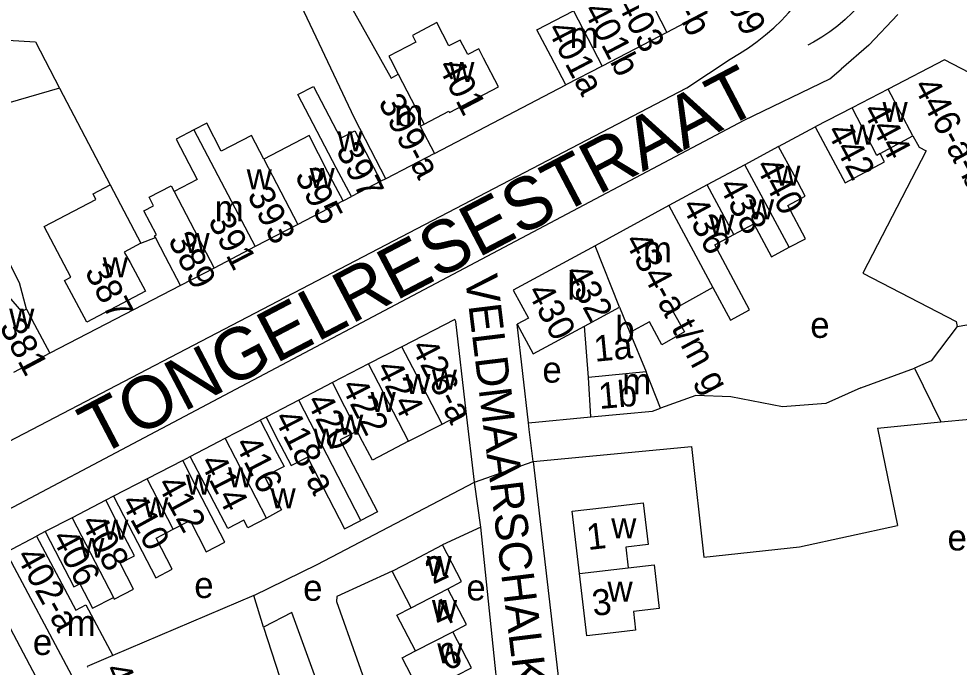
# Model space of a CAD drawing. Extents: x 163012 to 165277, y 382513 to 383987.
# Drawn here: x 163588.9 to 163733.4, y 383715.3 to 383815 of the extents above; entities that cross this region are included whole.
import ezdxf

# ---------------------------------------------------------------- set-up
doc = ezdxf.new("R2010")
doc.units = 0
for name, color, linetype in [('BLT_Basislijn', 7, 'Continuous'), ('BLT_Bebouwing', 7, 'Continuous'), ('BLT_Centroide', 7, 'Continuous'), ('BLT_Huisnummer', 7, 'Continuous'), ('BLT_Huisnummer_ tussenligend', 7, 'Continuous'), ('BLT_Huisnummer_reeks', 7, 'Continuous'), ('BLT_Onderverdeling_panden', 7, 'Continuous'), ('BLT_Straatnaam', 7, 'Continuous'), ('BLT_Straatnaam_hoofdweg', 7, 'Continuous'), ('BLT_Vlakafsluiter', 7, 'Continuous')]:
    doc.layers.add(name, color=color, linetype=linetype)

msp = doc.modelspace()

# ---------------------------------------------------------------- linework, layer by layer
at = {"layer": 'BLT_Basislijn'}
for p, q in [((163595.13, 383804.29), (163602.91, 383789.43)), ((163652.74, 383794.27), (163672.95, 383804.8)), ((163705.66, 383795.33), (163711.29, 383798.35)), ((163645.3, 383790.39), (163644.53, 383789.99)), ((163638.71, 383786.98), (163640.01, 383787.64)), ((163607.64, 383780.47), (163609.87, 383781.33)), ((163613.7, 383773.96), (163593.62, 383763.57)), ((163667.19, 383752.84), (163665.48, 383768.03)), ((163718.3, 383758.26), (163726.54, 383761.26)), ((163726.54, 383761.26), (163730.58, 383753.03)), ((163626.86, 383753.75), (163625.94, 383753.27)), ((163658.92, 383743.75), (163657.64, 383754.61)), ((163667.19, 383752.84), (163676.82, 383753.8)), ((163720.86, 383752.02), (163730.58, 383753.03)), ((163720.86, 383752.02), (163723.95, 383737.07)), ((163667.93, 383746.93), (163692.29, 383749.24)), ((163614.05, 383747.07), (163615.22, 383747.71)), ((163659.91, 383736.81), (163658.92, 383743.75)), ((163603.42, 383741.59), (163602.22, 383740.95)), ((163592.92, 383736.15), (163591.58, 383735.46)), ((163659.91, 383736.81), (163654, 383734.09)), ((163708.88, 383733.81), (163723.95, 383737.07)), ((163582.55, 383730.64), (163601.48, 383694.92))]:
    msp.add_line(p, q, dxfattribs=at)
for points in [[(163724.01, 383827.24), (163723.51, 383825.83), (163722.94, 383824.44), (163722.29, 383823.09), (163721.57, 383821.78), (163720.79, 383820.5), (163719.93, 383819.27), (163719.02, 383818.09), (163718.04, 383816.95), (163716.99, 383815.87), (163715.9, 383814.85), (163714.75, 383813.89), (163713.55, 383812.99), (163712.31, 383812.16), (163711.02, 383811.39), (163710.14, 383810.92)], [(163698.23, 383808.79), (163699.65, 383809.62), (163701.04, 383810.51), (163702.38, 383811.47), (163703.67, 383812.49), (163704.91, 383813.58), (163706.1, 383814.72), (163707.23, 383815.92), (163708.3, 383817.18), (163709.31, 383818.48), (163710.25, 383819.83), (163711.13, 383821.23), (163711.93, 383822.67), (163712.67, 383824.14), (163713.34, 383825.65), (163713.61, 383826.32)], [(163723.98, 383815.66), (163719.52, 383810.92), (163715.26, 383807.23)], [(163467.08, 383686.66), (163482.06, 383695.06), (163497.86, 383703.08), (163529.23, 383719.71), (163691.55, 383804.36), (163698.23, 383808.79)], [(163427.43, 383650.86), (163437.95, 383656.9), (163455.03, 383666.99), (163471.53, 383677.31), (163495.84, 383691.23), (163505.72, 383695.8), (163549.29, 383719.48), (163576.55, 383733.91), (163700.36, 383799.41), (163713.52, 383805.75), (163715.26, 383807.23)], [(163590.02, 383770.34), (163588.94, 383774.36), (163582.58, 383786.87)], [(163733.1, 383767.67), (163729.14, 383762.41), (163726.54, 383761.26)], [(163718.3, 383758.26), (163712.93, 383755.83), (163706.26, 383755.3)], [(163730.58, 383753.03), (163739.54, 383753.86), (163759.18, 383758.11)], [(163706.26, 383755.3), (163698.31, 383756.87), (163692.92, 383757.08), (163687.51, 383755.13)], [(163667.93, 383746.93), (163667.31, 383751.85), (163667.19, 383752.84)], [(163692.29, 383749.24), (163694.15, 383732.2), (163708.88, 383733.81)], [(163667.93, 383746.93), (163674.89, 383687.03), (163677.03, 383683.37), (163679.74, 383681.51), (163681.27, 383680.98), (163685.7, 383680.74)], [(163624.97, 383726.31), (163634.7, 383731.1), (163658.92, 383743.75)], [(163659.45, 383689.12), (163664.53, 383691.81), (163659.91, 383736.81)], [(163646.24, 383730.06), (163637.73, 383726.14), (163637.69, 383725.42), (163643.96, 383707.78), (163637.73, 383704.71)]]:
    msp.add_lwpolyline(points, dxfattribs=at)
at = {"layer": 'BLT_Bebouwing'}
for p, q in [((163695.01, 383816.28), (163688.49, 383812.89)), ((163688.49, 383812.89), (163678.52, 383807.7)), ((163731.14, 383808.68), (163722.48, 383804.17)), ((163735.02, 383806.65), (163731.14, 383808.68)), ((163678.52, 383807.7), (163672.95, 383804.8)), ((163595.13, 383804.29), (163575.89, 383798.75)), ((163722.48, 383804.17), (163716.96, 383801.3)), ((163716.96, 383801.3), (163711.29, 383798.35)), ((163721.25, 383794.28), (163726.32, 383796.99)), ((163705.66, 383795.33), (163700.47, 383792.54)), ((163652.74, 383794.27), (163645.3, 383790.39)), ((163700.47, 383792.54), (163694.69, 383789.43)), ((163644.53, 383789.99), (163640.01, 383787.64)), ((163602.91, 383789.43), (163607.64, 383780.47)), ((163694.69, 383789.43), (163688.78, 383786.26)), ((163638.71, 383786.98), (163631.75, 383783.36)), ((163688.78, 383786.26), (163677.47, 383780.07)), ((163631.75, 383783.36), (163625.21, 383779.96)), ((163698.8, 383781.79), (163701.84, 383783.43)), ((163607.64, 383780.47), (163605.07, 383779.11)), ((163625.21, 383779.96), (163618.87, 383776.66)), ((163618.87, 383776.66), (163613.7, 383773.96)), ((163718.61, 383775.89), (163732.96, 383768.43)), ((163695.57, 383773.66), (163698.27, 383768.65)), ((163732.96, 383768.43), (163733.1, 383767.67)), ((163676.43, 383759.84), (163675.81, 383767.73)), ((163682.8, 383766.74), (163685.31, 383760.72)), ((163593.62, 383763.57), (163588.02, 383760.6)), ((163647.76, 383764.57), (163642.63, 383761.92)), ((163642.63, 383761.92), (163637.07, 383759.04)), ((163687.51, 383755.13), (163685.31, 383760.72)), ((163676.82, 383753.8), (163676.43, 383759.84)), ((163637.07, 383759.04), (163631.89, 383756.35)), ((163631.89, 383756.35), (163626.86, 383753.75)), ((163620.58, 383750.49), (163625.94, 383753.27)), ((163614.05, 383747.07), (163608.58, 383744.25)), ((163608.58, 383744.25), (163603.42, 383741.59)), ((163602.22, 383740.95), (163597.05, 383738.28)), ((163597.05, 383738.28), (163592.92, 383736.15)), ((163586.94, 383733), (163591.58, 383735.46)), ((163591.58, 383735.46), (163597.62, 383724.04)), ((163596.99, 383714), (163586.94, 383733)), ((163649.16, 383724.43), (163646.24, 383730.06)), ((163624.97, 383726.31), (163603.29, 383717.08)), ((163626.49, 383721.47), (163624.97, 383726.31)), ((163597.62, 383724.04), (163599.17, 383724.86)), ((163599.17, 383724.86), (163603.29, 383717.08))]:
    msp.add_line(p, q, dxfattribs=at)
for points in [[(163645.3, 383790.39), (163642.99, 383794.83), (163640.44, 383799.72), (163630.94, 383819.87), (163638.85, 383818.87), (163646.08, 383805.86), (163647.2, 383806.44)], [(163672.95, 383804.8), (163670.63, 383809.23), (163668.52, 383813.27), (163674.15, 383816.22)], [(163660.31, 383808.94), (163659.56, 383810.37), (163657.87, 383809.49), (163656.72, 383811.71), (163654.99, 383810.81), (163653.13, 383814.38), (163649.37, 383812.42), (163649.91, 383811.38), (163645.76, 383809.22), (163645.99, 383808.77), (163647.2, 383806.44)], [(163582.76, 383811.96), (163591.41, 383811.42), (163595.13, 383804.29)], [(163651.18, 383798.79), (163654.95, 383800.75), (163655.05, 383800.58), (163662.62, 383804.5), (163660.31, 383808.94)], [(163640.01, 383787.64), (163637.67, 383792.05), (163635.89, 383795.41), (163631.77, 383803.32), (163634.16, 383804.56), (163638.3, 383796.61), (163640.49, 383797.75), (163642.23, 383794.43), (163644.53, 383789.99)], [(163626.53, 383793.38), (163624.63, 383797.04), (163619.99, 383794.62), (163617.75, 383798.93), (163615.77, 383797.9)], [(163650.55, 383798.46), (163651.18, 383798.79)], [(163650.55, 383798.46), (163652.74, 383794.27)], [(163711.29, 383798.35), (163713.64, 383793.94), (163715.89, 383789.74), (163721.95, 383792.98), (163721.25, 383794.28)], [(163615.77, 383797.9), (163613.04, 383796.48), (163616.28, 383790.26), (163612.75, 383788.42)], [(163638.71, 383786.98), (163636.38, 383791.42), (163633.51, 383797.01), (163626.53, 383793.38)], [(163726.32, 383796.99), (163727.25, 383795.25), (163728.37, 383794.67), (163718.61, 383775.89)], [(163707.29, 383779.85), (163709.81, 383781.14), (163707.06, 383786.25), (163709.76, 383787.7), (163708.03, 383790.93), (163705.66, 383795.33)], [(163605.07, 383779.11), (163605.97, 383777.52), (163608.32, 383773.1), (163599.31, 383768.32), (163596.96, 383772.74), (163595.9, 383774.73), (163596.88, 383775.26), (163592.78, 383783.02), (163600.72, 383787.21), (163600.3, 383788.05), (163602.91, 383789.43)], [(163609.87, 383781.33), (163609.73, 383781.59), (163610.03, 383781.74), (163608.09, 383785.47), (163609.57, 383786.24), (163608.9, 383787.54), (163612.29, 383789.3), (163612.75, 383788.42)], [(163701.84, 383783.43), (163704.55, 383778.38), (163707.29, 383779.85)], [(163613.7, 383773.96), (163611.39, 383778.4), (163609.87, 383781.33)], [(163698.27, 383768.65), (163701.21, 383770.22), (163695.84, 383780.2), (163698.8, 383781.79)], [(163677.47, 383780.07), (163664.86, 383773.28), (163667.2, 383768.95), (163665.48, 383768.03)], [(163590.02, 383770.34), (163589.33, 383769.98), (163586.67, 383773.06), (163584.96, 383776.24), (163581.13, 383774.13)], [(163695.57, 383773.66), (163689.32, 383770.18), (163691.22, 383766.83), (163687.72, 383764.87), (163685.81, 383768.38), (163682.8, 383766.74)], [(163733.1, 383767.67), (163751.44, 383770.83), (163756.37, 383771.68)], [(163590.02, 383770.34), (163591.27, 383767.99), (163593.62, 383763.57)], [(163657.64, 383754.61), (163656.02, 383768.46), (163655.88, 383768.75), (163647.76, 383764.57)], [(163665.48, 383768.03), (163667.93, 383763.48), (163675.81, 383767.73)], [(163676.82, 383753.8), (163681.8, 383754.24), (163686.28, 383754.65), (163687.51, 383755.13)], [(163626.86, 383753.75), (163628.8, 383750), (163629.16, 383749.31), (163630.72, 383746.3), (163633.23, 383747.6), (163638.95, 383736.56), (163641.46, 383737.86)], [(163653.92, 383752.68), (163657.64, 383754.61)], [(163625.94, 383753.27), (163627.63, 383750), (163628.24, 383748.83), (163629.63, 383746.14), (163626.64, 383744.59), (163629.26, 383739.51), (163626.95, 383738.2)], [(163648.79, 383750.03), (163653.92, 383752.68)], [(163615.22, 383747.71), (163619.63, 383750), (163620.58, 383750.49)], [(163640.86, 383751.57), (163638.27, 383750.26), (163638.37, 383749.98), (163643.98, 383739.16), (163641.46, 383737.86)], [(163648.79, 383750.03), (163643.24, 383747.1), (163641.71, 383750), (163640.86, 383751.57)], [(163626.95, 383738.2), (163624.08, 383736.71), (163623.46, 383737.91), (163620.97, 383736.61), (163618.91, 383740.59), (163617.52, 383743.28), (163615.22, 383747.71)], [(163612.57, 383736.5), (163615.19, 383737.86), (163617.67, 383733.05), (163620.53, 383734.52), (163616.34, 383742.63), (163614.05, 383747.07)], [(163603.39, 383726.01), (163603.52, 383725.74), (163606.49, 383727.27), (163604.42, 383731.29), (163606.62, 383732.42), (163604.51, 383736.5), (163602.22, 383740.95)], [(163603.42, 383741.59), (163605.72, 383737.15), (163609.91, 383729.05), (163612.41, 383730.39), (163609.95, 383735.15), (163612.57, 383736.5)], [(163675.03, 383729.71), (163673.91, 383739.29), (163678.88, 383739.87), (163684.83, 383740.57), (163685.59, 383734.14), (163682.19, 383733.74), (163682.56, 383730.59)], [(163592.92, 383736.15), (163595.21, 383731.71), (163597.31, 383727.63), (163598.24, 383728.1), (163600.18, 383724.35), (163603.39, 383726.01)], [(163646.24, 383730.06), (163649.53, 383731.77), (163654, 383734.09)], [(163654.83, 383727.36), (163656.92, 383728.45), (163654, 383734.09)], [(163682.56, 383730.59), (163686.53, 383731.05), (163687.32, 383724.32), (163683.35, 383723.85), (163683.68, 383721), (163681.12, 383720.7), (163676.16, 383720.12), (163675.03, 383729.71)], [(163655.59, 383720.75), (163657.69, 383721.84), (163654.83, 383727.36)], [(163649.84, 383717.79), (163646.99, 383723.3), (163649.16, 383724.43)], [(163637.73, 383704.71), (163630.85, 383723.71), (163626.49, 383721.47)], [(163656.27, 383714.09), (163658.46, 383715.22), (163655.59, 383720.75)], [(163650.67, 383711.19), (163647.8, 383716.73), (163649.84, 383717.79)]]:
    msp.add_lwpolyline(points, dxfattribs=at)
at = {"layer": 'BLT_Onderverdeling_panden'}
for p, q in [((163678.04, 383833.05), (163688.49, 383812.89)), ((163674.15, 383816.22), (163678.52, 383807.7)), ((163647.2, 383806.44), (163651.18, 383798.79)), ((163726.32, 383796.99), (163722.48, 383804.17)), ((163615.77, 383797.9), (163625.21, 383779.96)), ((163626.53, 383793.38), (163631.75, 383783.36)), ((163707.29, 383779.85), (163700.47, 383792.54)), ((163612.75, 383788.42), (163618.87, 383776.66)), ((163698.8, 383781.79), (163694.69, 383789.43)), ((163688.78, 383786.26), (163695.57, 383773.66)), ((163681.18, 383770.62), (163677.47, 383780.07)), ((163675.81, 383767.73), (163681.18, 383770.62)), ((163681.18, 383770.62), (163682.8, 383766.74)), ((163651.62, 383757.12), (163647.76, 383764.57)), ((163648.79, 383750.03), (163642.63, 383761.92)), ((163685.31, 383760.72), (163676.43, 383759.84)), ((163640.86, 383751.57), (163637.07, 383759.04)), ((163641.46, 383737.86), (163631.89, 383756.35)), ((163653.92, 383752.68), (163651.62, 383757.12)), ((163626.95, 383738.2), (163620.58, 383750.49)), ((163612.57, 383736.5), (163608.58, 383744.25)), ((163597.05, 383738.28), (163603.39, 383726.01)), ((163675.03, 383729.71), (163682.56, 383730.59)), ((163649.16, 383724.43), (163654.83, 383727.36)), ((163626.49, 383721.47), (163632.12, 383704.04)), ((163649.84, 383717.79), (163655.59, 383720.75)), ((163603.29, 383717.08), (163599.39, 383715.42)), ((163599.39, 383715.42), (163599.44, 383715.3))]:
    msp.add_line(p, q, dxfattribs=at)
msp.add_lwpolyline([(163721.25, 383794.28), (163720.78, 383793.94), (163716.96, 383801.3)], dxfattribs=at)
at = {"layer": 'BLT_Vlakafsluiter'}
msp.add_line((163658.92, 383743.75), (163667.93, 383746.93), dxfattribs=at)

# ---------------------------------------------------------------- texts
at = {"layer": 'BLT_Centroide'}
for s, p in [('m', (163673.52, 383810.48)), ('w', (163655.03, 383805.25)), ('m', (163646.59, 383798.59)), ('w', (163721.64, 383799.11)), ('w', (163716.62, 383795.62)), ('w', (163637.83, 383794.62)), ('w', (163705.14, 383789.3)), ('w', (163623.89, 383788.77)), ('w', (163633.56, 383788.97)), ('m', (163618.98, 383783.84)), ('w', (163701.11, 383784.16)), ('w', (163694.98, 383781.78)), ('w', (163614.33, 383778.97)), ('m', (163684.8, 383777.52)), ('w', (163601.77, 383775.22)), ('b', (163673.2, 383771.78)), ('w', (163587.38, 383767.33)), ('b', (163680.56, 383765.27)), ('e', (163710.53, 383765.92)), ('e', (163669.35, 383759.04)), ('w', (163652.35, 383757.98)), ('w', (163648.28, 383757.3)), ('m', (163681.63, 383757.25)), ('w', (163642.94, 383754.52)), ('w', (163637.94, 383751.02)), ('w', (163634.16, 383748.89)), ('w', (163614.55, 383741.81)), ('w', (163621.02, 383742.97)), ('w', (163627.56, 383739.72)), ('w', (163608, 383738.34)), ('w', (163601.83, 383734.88)), ('w', (163679.93, 383735.12)), ('e', (163731.63, 383733.24)), ('w', (163598.16, 383732.11)), ('w', (163651.56, 383729.31)), ('e', (163615.83, 383725.93)), ('e', (163632.57, 383725.51)), ('e', (163657.66, 383725.56)), ('w', (163679.36, 383725.36)), ('w', (163652.37, 383722.53)), ('m', (163596.22, 383720.08)), ('e', (163591.02, 383717.17)), ('w', (163653.19, 383715.88))]:
    msp.add_text(s, height=4, dxfattribs=at).set_placement(p)
at = {"layer": 'BLT_Huisnummer'}
for s, rotation, p in [('401a', 297.5473, (163669.99, 383813.41)), ('401', 297.5025, (163653.18, 383807.71)), ('442', 298.1453, (163712.94, 383797.7)), ('397', 297.1565, (163637.54, 383794.81)), ('440', 298.2547, (163702, 383792.34)), ('438 ', 298.2751, (163696.35, 383789.32)), ('393', 297.5029, (163623.89, 383787.9)), ('436', 298.2751, (163690.68, 383786.23)), ('389', 297.4671, (163611.72, 383780.98)), ('387', 297.9896, (163598.9, 383776.13)), ('381', 297.9896, (163585.8, 383767.66)), ('1a', 5.6346, (163677.44, 383762.24)), ('1b', 5.0243, (163678.12, 383754.98)), ('422', 296.8896, (163638.32, 383758.52)), ('414', 297.2967, (163616.62, 383746.85)), ('410', 298.7671, (163604.47, 383740.7)), ('1', 6.6851, (163676.36, 383733.29)), ('406', 298.1578, (163593.84, 383735.22)), ('2', 25.5747, (163652.54, 383727.96)), ('3', 6.6717, (163677.2, 383723.14)), ('6', 26.4351, (163654.71, 383714.6)), ('404', 293.0735, (163601.95, 383714.97))]:
    msp.add_text(s, height=4, rotation=rotation, dxfattribs=at).set_placement(p)
at = {"layer": 'BLT_Huisnummer_ tussenligend'}
for s, rotation, p in [('444', 298.1453, (163718.48, 383800.89)), ('395', 297.5029, (163631.21, 383790.87)), ('391', 297.4671, (163617.87, 383783.94)), ('424', 296.8896, (163643.66, 383761.31)), ('420', 297.3651, (163632.98, 383756.21)), ('416', 297.2967, (163621.97, 383749.63)), ('412', 298.7671, (163610.01, 383743.46)), ('408', 298.1578, (163598.28, 383737.58)), ('4', 25.5747, (163653.52, 383721.22))]:
    msp.add_text(s, height=4, rotation=rotation, dxfattribs=at).set_placement(p)
at = {"layer": 'BLT_Huisnummer_reeks'}
for s, rotation, p in [('405t/m409', 297.6369, (163688.68, 383834.44)), ('403a-b', 297.3977, (163684.36, 383826.77)), ('403', 297.1591, (163680.71, 383817.4)), ('401b', 297.5473, (163675.55, 383816.32)), ('446-a-b', 298.152, (163726.3, 383804.65)), ('399-a', 297.5092, (163644.04, 383802.17)), ('434-a t/m g', 298.3178, (163681.89, 383780.85)), ('432', 298.3178, (163672.62, 383775.94)), ('430', 298.3178, (163666.92, 383773.04)), ('426-a', 297.3763, (163649.08, 383764.53)), ('418-a', 297.3651, (163628, 383753.63)), ('402-a', 299, (163588.34, 383732.39))]:
    msp.add_text(s, height=4, rotation=rotation, dxfattribs=at).set_placement(p)
at = {"layer": 'BLT_Straatnaam'}
msp.add_text('VELDMAARSCHALK SMUTSSTRAAT', height=5, rotation=276.9537, dxfattribs=at).set_placement((163657.43, 383775.37))
at = {"layer": 'BLT_Straatnaam_hoofdweg'}
msp.add_text('TONGELRESESTRAAT', height=8, rotation=27.617, dxfattribs=at).set_placement((163600.99, 383747.59))

doc.saveas('drawing.dxf')
